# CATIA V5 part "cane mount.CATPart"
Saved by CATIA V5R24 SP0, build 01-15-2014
Part number: cane mount
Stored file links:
  C:\Users\Z\Documents\Inventor\MariahStaff\cane mount.CATPart

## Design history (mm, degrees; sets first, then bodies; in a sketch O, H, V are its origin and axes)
Body1 "Solid3" (main body)
  Solid1: solid without history
Body2 "Solid4"
  Solid2: solid without history
Body3 "Solid14"
  Solid3: solid without history
Body4 "Solid17"
  Solid4: solid without history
